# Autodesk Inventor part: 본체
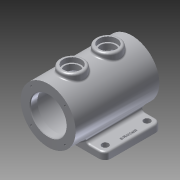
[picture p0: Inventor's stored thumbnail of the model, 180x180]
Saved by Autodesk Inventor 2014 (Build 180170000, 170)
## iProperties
Created: 2014-12
Part Number: 본체
Material: 알루미늄 6061
Document SubType Name: Modeling
Designer: Owner
Mass: 1295.01 g
Surface Area: 1028.66 cm^2
Volume: 477.863 cm^3
Density: 2.71 g/cm^3
Appearance: 알루미늄 - 평지
Author: Owner
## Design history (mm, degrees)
sketch "스케치1"
  geometry: C1 r 46 at (0, 0); 1 further point
  constraints: 1 centre point, 1 coincident
  dimensions: "d0" = 92 diameter of C1
extrude "돌출1" new body sketch "스케치1" stored distance "d1" = 140; taper "d2" = 0 deg
sketch "스케치2"
  geometry: C1 r 46 at (0, 0) reference; 1 further point
  constraints: 1 coincident
hole "구멍1" sketch "스케치2" at (0, 0) diameter "d3" = 60; stored, may be unused: countersink angle "d7" = 90 deg, drill point angle "d9" = 0 deg; dims "d4" = 6, "d5" = 4, "d6" = 2, "d8" = 12
sketch "스케치3"
  geometry: C1 r 30 at (0, 0) reference; 1 further point
  constraints: 1 coincident
hole "구멍2" sketch "스케치3" at (0, 0) diameter "d10" = 75; stored, may be unused: countersink angle "d14" = 90 deg, drill point angle "d16" = 0 deg; dims "d11" = 6, "d12" = 4, "d13" = 2, "d15" = 58
node "작업 평면1"
sketch "스케치4"
  geometry: C1 r 20 at (0, -30); 2 further points
  constraints: 1 centre point, 1 coincident, 1 vertical alignment
  dimensions: "d18" = 40 diameter of C1; "d19" = 30 distance of C1.centre point (0, 0)
extrude "돌출2" join sketch "스케치4" stored distance "d20" = 140; taper "d21" = 0 deg
node "작업 평면2"
sketch "스케치11"
  geometry: L1 (-65, -40)-(65, -40); L2 (65, -40)-(65, 55); L3 (65, 55)-(-65, 55); L4 (-65, 55)-(-65, -40); 2 further points
  constraints: 8 end point, 2 parallel, 1 horizontal, 1 midpoint, 1 perpendicular, 1 vertical alignment
  dimensions: "d44" = 40 distance from line of L1 point (0, 0); "d45" = 55 distance from line of L3 point (0, 0); "d46" = 130 distance of L2.end L3.end
extrude "돌출4" join sketch "스케치11" distance "d47" = 12; taper "d48" = 0 deg
sketch "스케치12"
  geometry: L1 (25.923, -40)-(65, -40) reference; L2 (65, -40)-(65, 55) reference; 2 further points
  constraints: 1 other
  dimensions: "d49" = 47.5 distance from line of point (57, 7.5) L1; "d50" = 8 distance from line of L2 point (57, 7.5)
feature "엠보싱1" sketch "스케치12" dims "d51" = 1, "d52" = 0
sketch "스케치13"
  geometry: L1 (25.923, -40)-(65, -40) reference; L2 (65, -40)-(65, 55) reference; 2 further points
  dimensions: "d53" = 12.5 distance from line of point (52.5, -27) L2; "d54" = 13 distance from line of point (52.5, -27) L1
hole "구멍5" sketch "스케치13" at (52.5, -27) diameter "d55" = 11; stored, may be unused: countersink angle "d59" = 90 deg, drill point angle "d61" = 0 deg; dims "d56" = 6, "d57" = 4, "d58" = 2, "d60" = 50
sketch "스케치14"
  geometry: L1 (0, 0)-(28.284, 28.284); L2 (0, 0)-(40, 0); C1 r 46 at (0, 0) reference; 1 further point
  constraints: 4 end point, 1 coincident, 1 equal length, 1 horizontal
  dimensions: "d68" = 40 distance of L1.start L1.end; "d69" = 45 deg angle of L2 L1
hole "구멍6" sketch "스케치14" at (28.284, 28.284) diameter "d70" = 3.242; stored, may be unused: countersink angle "d74" = 90 deg, drill point angle "d76" = 118 deg; dims "d71" = 8, "d72" = 4, "d73" = 2, "d75" = 10
fillet "모깎기1" dims "d80" = 3
fillet "모깎기2" dims "d81" = 5
fillet "모깎기5" dims "d84" = 3
fillet "모깎기6" dims "d85" = 10
fillet "모깎기7" dims "d86" = 3
chamfer "모따기1" distance "d87" = 1; stored, may be unused: second distance "d88" = 2, angle "d89" = 45 deg
fillet "모깎기8" dims "d90" = 3
sketch "스케치15"
  geometry: C1 r 17 at (0, 0) reference; 2 further points
  constraints: 1 coincident
hole "구멍7" sketch "스케치15" at (0, 0) diameter "d91" = 30; stored, may be unused: countersink angle "d95" = 90 deg, drill point angle "d97" = 0 deg; dims "d92" = 8, "d93" = 4, "d94" = 2, "d96" = 8
sketch "스케치16"
  geometry: C1 r 15 at (0, 0) reference; 2 further points
  constraints: 1 coincident
hole "구멍8" sketch "스케치16" at (0, 0) diameter "d98" = 25; stored, may be unused: countersink angle "d102" = 90 deg, drill point angle "d104" = 0 deg; dims "d99" = 8, "d100" = 4, "d101" = 2, "d103" = 40
node "작업 평면3"
sketch "스케치17"
  geometry: C1 r 20 at (0, 30); 1 further point
  constraints: 1 centre point, 1 vertical alignment
  dimensions: "d106" = 40 diameter of C1; "d107" = 30 distance of C1.centre point (0, 0)
extrude "돌출5" join sketch "스케치17" stored distance "d108" = 12; taper "d109" = 0 deg
sketch "스케치18"
  geometry: C1 r 20 at (0, 0) reference; 2 further points
  constraints: 1 coincident
hole "구멍9" sketch "스케치18" at (0, 0) diameter "d110" = 30; stored, may be unused: countersink angle "d114" = 90 deg, drill point angle "d116" = 0 deg; dims "d111" = 8, "d112" = 4, "d113" = 2, "d115" = 8
sketch "스케치19"
  geometry: C1 r 15 at (0, 0) reference; 2 further points
  constraints: 1 coincident
hole "구멍10" sketch "스케치19" at (0, 0) diameter "d117" = 25; stored, may be unused: countersink angle "d121" = 90 deg, drill point angle "d123" = 0 deg; dims "d118" = 8, "d119" = 4, "d120" = 2, "d122" = 40
fillet "모깎기9" dims "d124" = 3
node "솔리드1"
mirror "대칭1"
pattern_linear "직사각형 패턴1" dims "d64" = 70, "d67" = 104
pattern_circular "원형 패턴1" dims angle "d78" = 360 deg
mirror "대칭3"
other parameters: "d17" = 54, "d105" = 54
